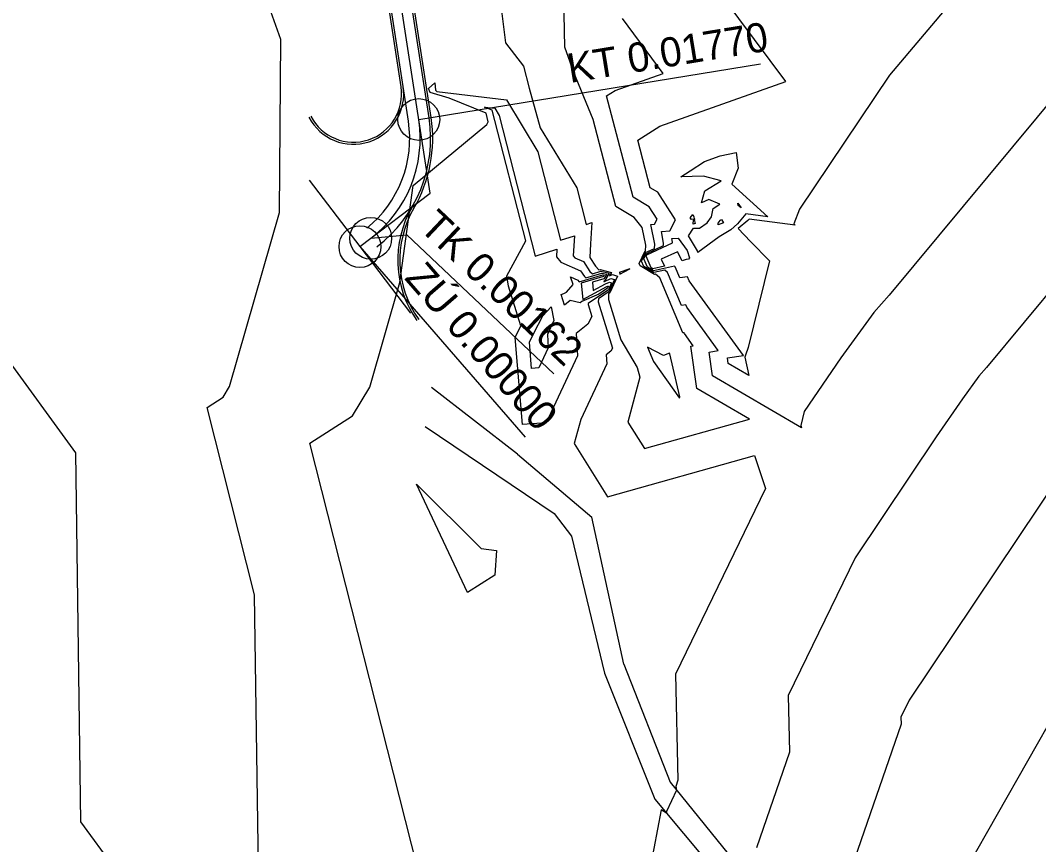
# Model space of a CAD drawing. Extents: x -549394 to -546608, y -1037055 to -1033629.
# Drawn here: x -547937.2 to -547815.5, y -1034670.8 to -1034572.2 of the extents above; entities that cross this region are included whole.
import ezdxf

# ---------------------------------------------------------------- set-up
doc = ezdxf.new("R2010")
doc.units = 0
for name, color, linetype in [('hlavni_vrst', 7, 'Continuous'), ('hrana_L', 7, 'Continuous'), ('norm_vrst', 7, 'Continuous'), ('POLYGONY_SITUACE_PO', 7, 'Continuous'), ('x_navrh_C211', 7, 'Continuous'), ('x_osa_C211', 7, 'Continuous'), ('x_popis_oblouky_C211', 7, 'Continuous'), ('x_popis_pricne_rezy_C211', 7, 'Continuous')]:
    doc.layers.add(name, color=color, linetype=linetype)

msp = doc.modelspace()

# ---------------------------------------------------------------- linework, layer by layer
at = {"layer": 'hlavni_vrst'}
for p, q in [((-547855.39, -1034589.11), (-547853.52, -1034588.45)), ((-547853.52, -1034588.45), (-547851.59, -1034588.02)), ((-547851.59, -1034588.02), (-547851.38, -1034589.9)), ((-547857.11, -1034590.21), (-547855.39, -1034589.11)), ((-547851.38, -1034589.9), (-547852.13, -1034591.83)), ((-547858.22, -1034590.96), (-547857.11, -1034590.21)), ((-547855.5, -1034590.85), (-547858.22, -1034590.96)), ((-547853.38, -1034591.44), (-547855.5, -1034590.85)), ((-547855.35, -1034592.64), (-547853.38, -1034591.44)), ((-547852.13, -1034591.83), (-547847.81, -1034595.73)), ((-547855.76, -1034594.07), (-547855.35, -1034592.64)), ((-547854.86, -1034593.64), (-547855.76, -1034594.07)), ((-547853.54, -1034594.23), (-547854.86, -1034593.64)), ((-547854.55, -1034595.72), (-547854.35, -1034594.72)), ((-547854.35, -1034594.72), (-547853.54, -1034594.23)), ((-547857.09, -1034595.86), (-547856.79, -1034595.47)), ((-547856.93, -1034596.05), (-547857.09, -1034595.86)), ((-547856.67, -1034596.02), (-547856.93, -1034596.05)), ((-547856.79, -1034595.47), (-547856.67, -1034595.74)), ((-547856.75, -1034596.43), (-547856.67, -1034596.02)), ((-547856.67, -1034595.74), (-547856.63, -1034595.97)), ((-547856.63, -1034595.97), (-547856.54, -1034595.99)), ((-547856.54, -1034595.99), (-547856.61, -1034596.04)), ((-547856.61, -1034596.04), (-547856.51, -1034596.53)), ((-547855.08, -1034596.46), (-547854.55, -1034595.72)), ((-547850.46, -1034595.39), (-547851.43, -1034596.58)), ((-547847.81, -1034595.73), (-547850.46, -1034595.39)), ((-547857.31, -1034598.01), (-547856.71, -1034597.1)), ((-547856.75, -1034596.62), (-547856.75, -1034596.43)), ((-547856.51, -1034596.53), (-547856.75, -1034596.62)), ((-547856.71, -1034597.1), (-547855.99, -1034597.1)), ((-547855.99, -1034597.1), (-547855.08, -1034596.46)), ((-547852.25, -1034597.27), (-547853.65, -1034598.14)), ((-547851.43, -1034596.58), (-547852.25, -1034597.27)), ((-547859.29, -1034598.34), (-547858.54, -1034598.29)), ((-547859.21, -1034598.74), (-547859.29, -1034598.34)), ((-547858.54, -1034598.29), (-547857.47, -1034599.77)), ((-547856.22, -1034599.79), (-547857.31, -1034598.01)), ((-547853.65, -1034598.14), (-547856.17, -1034599.98)), ((-547862.27, -1034600.28), (-547859.21, -1034598.83)), ((-547859.21, -1034598.83), (-547859.21, -1034598.74)), ((-547857.47, -1034599.77), (-547857.18, -1034600.64)), ((-547856.17, -1034599.98), (-547856.22, -1034599.79)), ((-547862.35, -1034600.45), (-547862.27, -1034600.28)), ((-547861.77, -1034601.83), (-547862.35, -1034600.45)), ((-547858.62, -1034599.9), (-547860.55, -1034600.8)), ((-547860.55, -1034600.8), (-547860.17, -1034601.64)), ((-547858.05, -1034601.01), (-547858.62, -1034599.9)), ((-547857.6, -1034600.85), (-547858.05, -1034601.01)), ((-547857.3, -1034600.78), (-547857.6, -1034600.85)), ((-547857.18, -1034600.64), (-547857.3, -1034600.78)), ((-547861.56, -1034601.95), (-547861.77, -1034601.83)), ((-547860.17, -1034601.64), (-547861.56, -1034601.95)), ((-547871.41, -1034602.91), (-547870.53, -1034603.29)), ((-547871.07, -1034603.84), (-547871.41, -1034602.91)), ((-547870.53, -1034603.29), (-547870.41, -1034603.48)), ((-547870.36, -1034603.52), (-547867.54, -1034602.68)), ((-547867.48, -1034602.88), (-547870.14, -1034603.67)), ((-547867.54, -1034602.68), (-547867.38, -1034602.72)), ((-547867.38, -1034602.72), (-547867.48, -1034602.88)), ((-547871.87, -1034604.75), (-547871.07, -1034603.84)), ((-547870.41, -1034603.48), (-547870.36, -1034603.52)), ((-547870.14, -1034603.67), (-547869.95, -1034605.6)), ((-547869.95, -1034605.6), (-547867.06, -1034604.07)), ((-547866.97, -1034604.26), (-547868.02, -1034604.99)), ((-547867.06, -1034604.07), (-547866.93, -1034604.01)), ((-547866.86, -1034604.03), (-547866.97, -1034604.26)), ((-547866.93, -1034604.01), (-547866.86, -1034604.03)), ((-547872.51, -1034605.03), (-547872.22, -1034604.89)), ((-547872.11, -1034606.3), (-547872.51, -1034605.03)), ((-547872.22, -1034604.89), (-547871.87, -1034604.75)), ((-547871.44, -1034605.75), (-547872.11, -1034606.3)), ((-547870.26, -1034606.01), (-547871.44, -1034605.75)), ((-547870.06, -1034605.85), (-547870.26, -1034606.01)), ((-547868.02, -1034604.99), (-547870.06, -1034605.85)), ((-547874.72, -1034607.57), (-547873.72, -1034606.48)), ((-547873.72, -1034606.48), (-547873.4, -1034608.13)), ((-547875.77, -1034609.63), (-547874.72, -1034607.57)), ((-547873.4, -1034608.13), (-547874.17, -1034609.82)), ((-547876.31, -1034610.73), (-547875.77, -1034609.63)), ((-547876.06, -1034613.86), (-547876.31, -1034610.73)), ((-547874.17, -1034609.82), (-547874.08, -1034611.38)), ((-547874.08, -1034611.38), (-547875.2, -1034613.8)), ((-547875.2, -1034613.8), (-547876.06, -1034613.86)), ((-547813.16, -1034654.45), (-547828.03, -1034680.56))]:
    msp.add_line(p, q, dxfattribs=at)
at = {"layer": 'hrana_L'}
for p, q in [((-547877.75, -1034624.13), (-547888.02, -1034616.15)), ((-547888.78, -1034620.79), (-547873.35, -1034631.21)), ((-547877.75, -1034624.13), (-547868.85, -1034631.65)), ((-547873.35, -1034631.21), (-547871.3, -1034633.92)), ((-547865.04, -1034649.22), (-547868.85, -1034631.65)), ((-547871.3, -1034633.92), (-547867.33, -1034650.32)), ((-547865.04, -1034649.22), (-547859.51, -1034663.34)), ((-547867.33, -1034650.32), (-547861.32, -1034665.38)), ((-547859.51, -1034663.34), (-547833.31, -1034695.61)), ((-547861.32, -1034665.38), (-547834.9, -1034696.97))]:
    msp.add_line(p, q, dxfattribs=at)
at = {"layer": 'norm_vrst'}
for p, q in [((-547882.84, -1034544.56), (-547879.18, -1034574.92)), ((-547845.65, -1034579.54), (-547858.44, -1034562.37)), ((-547820.19, -1034563.23), (-547833.27, -1034578.79)), ((-547906.03, -1034574.52), (-547908.1, -1034568.67)), ((-547872.08, -1034575.43), (-547872.21, -1034569.2)), ((-547860.31, -1034578.59), (-547865.2, -1034572.02)), ((-547906.18, -1034595.2), (-547906.03, -1034574.52)), ((-547879.18, -1034574.92), (-547877.04, -1034577.71)), ((-547871.01, -1034578.47), (-547872.08, -1034575.43)), ((-547877.04, -1034577.71), (-547876.33, -1034580.33)), ((-547868.69, -1034584.09), (-547871.01, -1034578.47)), ((-547866.08, -1034580.63), (-547860.31, -1034578.59)), ((-547833.27, -1034578.79), (-547844.05, -1034594.82)), ((-547888.36, -1034580.39), (-547887.63, -1034579.69)), ((-547887.63, -1034579.69), (-547887.52, -1034580.57)), ((-547860.73, -1034584.87), (-547845.65, -1034579.54)), ((-547812.36, -1034579.85), (-547833.3, -1034605.08)), ((-547888.19, -1034580.88), (-547888.36, -1034580.39)), ((-547885.9, -1034581.53), (-547888.19, -1034580.88)), ((-547887.52, -1034580.57), (-547887.38, -1034580.75)), ((-547887.38, -1034580.75), (-547879.07, -1034581.73)), ((-547881.5, -1034583.33), (-547885.9, -1034581.53)), ((-547876.33, -1034580.33), (-547875.03, -1034585.08)), ((-547867.09, -1034581.27), (-547866.08, -1034580.63)), ((-547863.92, -1034593.38), (-547867.09, -1034581.27)), ((-547880.78, -1034582.97), (-547881.68, -1034582.6)), ((-547881.68, -1034582.6), (-547880.45, -1034582.75)), ((-547880.45, -1034582.75), (-547879.93, -1034583.6)), ((-547879.07, -1034581.73), (-547875.29, -1034587.94)), ((-547881.24, -1034584.36), (-547881.5, -1034583.33)), ((-547876.75, -1034598.6), (-547880.78, -1034582.97)), ((-547879.93, -1034583.6), (-547875.62, -1034600.45)), ((-547890.21, -1034591.99), (-547881.42, -1034584.7)), ((-547881.42, -1034584.7), (-547881.24, -1034584.36)), ((-547875.03, -1034585.08), (-547870.65, -1034592.27)), ((-547865.97, -1034594.51), (-547868.69, -1034584.09)), ((-547863.37, -1034586.55), (-547860.73, -1034584.87)), ((-547861.88, -1034592.25), (-547863.37, -1034586.55)), ((-547875.29, -1034587.94), (-547872.58, -1034598.54)), ((-547891.8, -1034603.57), (-547890.21, -1034591.99)), ((-547870.65, -1034592.27), (-547869.53, -1034596.64)), ((-547860.97, -1034592.8), (-547861.88, -1034592.25)), ((-547861.99, -1034594.54), (-547863.92, -1034593.38)), ((-547858.85, -1034596.1), (-547860.97, -1034592.8)), ((-547863.8, -1034595.81), (-547865.97, -1034594.51)), ((-547861.04, -1034596.02), (-547861.99, -1034594.54)), ((-547851.39, -1034594.11), (-547850.99, -1034594.65)), ((-547851.38, -1034594.39), (-547851.39, -1034594.11)), ((-547850.99, -1034594.65), (-547851.38, -1034594.39)), ((-547844.05, -1034594.82), (-547844.73, -1034596.56)), ((-547912.15, -1034616.02), (-547906.18, -1034595.2)), ((-547862.82, -1034597.02), (-547863.8, -1034595.81)), ((-547861.35, -1034596.61), (-547861.04, -1034596.02)), ((-547859.53, -1034597.42), (-547858.85, -1034596.1)), ((-547853.52, -1034596.18), (-547853.51, -1034596.13)), ((-547853.51, -1034596.13), (-547853.36, -1034596.03)), ((-547853.36, -1034596.03), (-547853.12, -1034596.46)), ((-547850.07, -1034595.99), (-547850.22, -1034596.18)), ((-547844.56, -1034596.71), (-547850.07, -1034595.99)), ((-547869.53, -1034596.64), (-547868.86, -1034596.41)), ((-547868.86, -1034596.41), (-547869.02, -1034598.96)), ((-547862.4, -1034599.1), (-547862.82, -1034597.02)), ((-547861.8, -1034596.64), (-547861.35, -1034596.61)), ((-547861.34, -1034598.98), (-547861.8, -1034596.64)), ((-547853.12, -1034596.46), (-547853.77, -1034596.68)), ((-547853.77, -1034596.68), (-547853.74, -1034596.49)), ((-547853.74, -1034596.49), (-547853.52, -1034596.18)), ((-547850.22, -1034596.18), (-547851.35, -1034597.13)), ((-547851.35, -1034597.13), (-547849.91, -1034598.68)), ((-547844.73, -1034596.56), (-547844.56, -1034596.71)), ((-547872.58, -1034598.54), (-547870.94, -1034598)), ((-547870.94, -1034598), (-547871.09, -1034600.38)), ((-547860.54, -1034597.49), (-547859.53, -1034597.42)), ((-547860.27, -1034598.86), (-547860.54, -1034597.49)), ((-547879.03, -1034602.8), (-547876.75, -1034598.6)), ((-547875.62, -1034600.45), (-547873.02, -1034599.6)), ((-547873.02, -1034599.6), (-547873.08, -1034600.53)), ((-547869.02, -1034598.96), (-547869.11, -1034600.61)), ((-547862.46, -1034599.84), (-547862.4, -1034599.1)), ((-547862.43, -1034600.01), (-547861.38, -1034599.5)), ((-547862.35, -1034600.15), (-547860.29, -1034599.17)), ((-547861.38, -1034599.5), (-547861.34, -1034598.98)), ((-547860.29, -1034599.17), (-547860.27, -1034598.86)), ((-547849.91, -1034598.68), (-547847.64, -1034601.01)), ((-547873.08, -1034600.53), (-547872.55, -1034601.16)), ((-547871.09, -1034600.38), (-547870.87, -1034600.65)), ((-547870.87, -1034600.65), (-547869.85, -1034601.09)), ((-547869.11, -1034600.61), (-547868.43, -1034601.64)), ((-547863.18, -1034601.31), (-547862.51, -1034599.87)), ((-547862.9, -1034601.03), (-547862.43, -1034600.01)), ((-547862.63, -1034600.74), (-547862.35, -1034600.15)), ((-547862.2, -1034601.74), (-547862.63, -1034600.74)), ((-547862.51, -1034599.87), (-547862.46, -1034599.84)), ((-547872.55, -1034601.16), (-547870.19, -1034602.19)), ((-547870.19, -1034602.19), (-547869.75, -1034602.86)), ((-547869.85, -1034601.09), (-547869.09, -1034602.25)), ((-547868.43, -1034601.64), (-547868, -1034602.06)), ((-547868, -1034602.06), (-547867.86, -1034602.02)), ((-547867.86, -1034602.02), (-547866.49, -1034602.37)), ((-547864.33, -1034601.93), (-547865.57, -1034602.37)), ((-547865.49, -1034602.6), (-547864.33, -1034601.93)), ((-547863.07, -1034601.58), (-547863.18, -1034601.31)), ((-547861.37, -1034602.61), (-547863.07, -1034601.58)), ((-547862.63, -1034601.66), (-547862.9, -1034601.03)), ((-547861.43, -1034602.39), (-547862.63, -1034601.66)), ((-547861.5, -1034602.17), (-547862.2, -1034601.74)), ((-547858.99, -1034601.62), (-547861.5, -1034602.17)), ((-547860.12, -1034602.1), (-547861.43, -1034602.39)), ((-547859.8, -1034602.37), (-547860.12, -1034602.1)), ((-547858.89, -1034601.71), (-547858.99, -1034601.62)), ((-547858.34, -1034603.03), (-547858.89, -1034601.71)), ((-547847.64, -1034601.01), (-547850.19, -1034611.37)), ((-547811.34, -1034601.27), (-547821.7, -1034613.75)), ((-547878.82, -1034604.04), (-547879.03, -1034602.8)), ((-547869.75, -1034602.86), (-547869.57, -1034603.04)), ((-547869.57, -1034603.04), (-547867.65, -1034602.46)), ((-547869.09, -1034602.25), (-547868.79, -1034602.55)), ((-547868.79, -1034602.55), (-547867.76, -1034602.24)), ((-547867.42, -1034603.15), (-547868.79, -1034603.55)), ((-547867.76, -1034602.24), (-547866.79, -1034602.48)), ((-547867.65, -1034602.46), (-547867.08, -1034602.6)), ((-547867.36, -1034603.42), (-547867.43, -1034603.44)), ((-547867.43, -1034603.44), (-547867.42, -1034603.48)), ((-547867.08, -1034602.6), (-547867.42, -1034603.15)), ((-547866.79, -1034602.48), (-547867.36, -1034603.42)), ((-547867.35, -1034603.45), (-547866.57, -1034603.09)), ((-547866.15, -1034603.22), (-547866.79, -1034604.64)), ((-547866.49, -1034602.37), (-547866.76, -1034602.8)), ((-547866.76, -1034602.8), (-547866.39, -1034602.64)), ((-547865.8, -1034602.81), (-547866.7, -1034604.83)), ((-547866.57, -1034603.09), (-547866.15, -1034603.22)), ((-547866.39, -1034602.64), (-547865.8, -1034602.81)), ((-547865.57, -1034602.37), (-547865.44, -1034602.41)), ((-547865.44, -1034602.41), (-547865.49, -1034602.5)), ((-547865.49, -1034602.5), (-547865.49, -1034602.6)), ((-547861.25, -1034602.58), (-547861.37, -1034602.61)), ((-547860.72, -1034603.02), (-547861.25, -1034602.58)), ((-547857.97, -1034609.62), (-547860.72, -1034603.02)), ((-547858.15, -1034606.33), (-547859.8, -1034602.37)), ((-547857.43, -1034602.92), (-547858.34, -1034603.03)), ((-547857.22, -1034603.37), (-547857.43, -1034602.92)), ((-547850.74, -1034612.33), (-547857.22, -1034603.37)), ((-547895.39, -1034616.11), (-547891.8, -1034603.57)), ((-547877.33, -1034608.76), (-547878.82, -1034604.04)), ((-547866.88, -1034604.45), (-547869.28, -1034606.1)), ((-547868.79, -1034603.55), (-547868.69, -1034604.54)), ((-547868.69, -1034604.54), (-547867.21, -1034603.76)), ((-547866.79, -1034604.64), (-547868.07, -1034605.52)), ((-547867.42, -1034603.48), (-547867.35, -1034603.45)), ((-547867.21, -1034603.76), (-547866.75, -1034603.55)), ((-547866.51, -1034603.63), (-547866.88, -1034604.45)), ((-547866.75, -1034603.55), (-547866.51, -1034603.63)), ((-547868.07, -1034605.52), (-547868.08, -1034605.91)), ((-547866.85, -1034604.93), (-547866.87, -1034605.62)), ((-547866.87, -1034605.62), (-547865.4, -1034610.42)), ((-547866.7, -1034604.83), (-547866.85, -1034604.93)), ((-547833.3, -1034605.08), (-547835.14, -1034607.17)), ((-547869.28, -1034606.1), (-547869.29, -1034606.21)), ((-547869.29, -1034606.21), (-547868.85, -1034607.64)), ((-547868.08, -1034605.91), (-547866.39, -1034611.42)), ((-547857.63, -1034606.27), (-547858.15, -1034606.33)), ((-547857.51, -1034606.52), (-547857.63, -1034606.27)), ((-547853.74, -1034611.73), (-547857.51, -1034606.52)), ((-547868.85, -1034607.64), (-547869.34, -1034608.56)), ((-547835.14, -1034607.17), (-547839.08, -1034612.61)), ((-547878.02, -1034610.16), (-547877.33, -1034608.76)), ((-547869.34, -1034608.56), (-547870.73, -1034609.7)), ((-547877.16, -1034620.57), (-547878.02, -1034610.16)), ((-547870.73, -1034609.7), (-547870.58, -1034612.35)), ((-547865.4, -1034610.42), (-547863.43, -1034613.73)), ((-547857.82, -1034609.61), (-547857.97, -1034609.62)), ((-547857.79, -1034609.68), (-547857.82, -1034609.61)), ((-547856.73, -1034611.14), (-547857.79, -1034609.68)), ((-547930.54, -1034623.95), (-547939.34, -1034611.82)), ((-547866.59, -1034611.79), (-547867.14, -1034612.25)), ((-547866.39, -1034611.42), (-547866.59, -1034611.79)), ((-547860.29, -1034612.3), (-547862.19, -1034611.32)), ((-547862.19, -1034611.32), (-547861.5, -1034613.04)), ((-547857.04, -1034611.19), (-547856.73, -1034611.14)), ((-547856.32, -1034616.26), (-547857.04, -1034611.19)), ((-547854.85, -1034611.9), (-547853.74, -1034611.73)), ((-547854.44, -1034614.76), (-547854.85, -1034611.9)), ((-547850.19, -1034611.37), (-547850.5, -1034612.28)), ((-547870.58, -1034612.35), (-547874.32, -1034620.37)), ((-547867.14, -1034612.25), (-547867.08, -1034613.31)), ((-547861.5, -1034613.04), (-547858.39, -1034617.41)), ((-547859.57, -1034612.02), (-547860.29, -1034612.3)), ((-547859.55, -1034612.1), (-547859.57, -1034612.02)), ((-547858.33, -1034617.24), (-547859.55, -1034612.1)), ((-547852.65, -1034612.61), (-547850.74, -1034612.33)), ((-547852.56, -1034613.27), (-547852.65, -1034612.61)), ((-547850.5, -1034612.28), (-547850.55, -1034612.5)), ((-547850.55, -1034612.5), (-547850.1, -1034614.7)), ((-547839.08, -1034612.61), (-547843.48, -1034619.01)), ((-547867.08, -1034613.31), (-547870.18, -1034619.95)), ((-547863.43, -1034613.73), (-547863.1, -1034614.91)), ((-547850.1, -1034614.7), (-547852.56, -1034613.27)), ((-547821.7, -1034613.75), (-547822.61, -1034614.79)), ((-547863.1, -1034614.91), (-547864.54, -1034620.27)), ((-547843.8, -1034620.95), (-547854.44, -1034614.76)), ((-547822.61, -1034614.79), (-547824.57, -1034617.48)), ((-547912.92, -1034617.31), (-547912.15, -1034616.02)), ((-547897.44, -1034619.54), (-547895.39, -1034616.11)), ((-547850.02, -1034619.92), (-547856.32, -1034616.26)), ((-547914.83, -1034618.53), (-547912.92, -1034617.31)), ((-547858.39, -1034617.41), (-547858.33, -1034617.24)), ((-547824.57, -1034617.48), (-547827.69, -1034622.02)), ((-547909.16, -1034640.94), (-547914.83, -1034618.53)), ((-547843.48, -1034619.01), (-547843.86, -1034620.68)), ((-547902.54, -1034622.79), (-547897.44, -1034619.54)), ((-547874.32, -1034620.37), (-547877.16, -1034620.57)), ((-547870.18, -1034619.95), (-547870.95, -1034622.83)), ((-547864.54, -1034620.27), (-547862.57, -1034623.45)), ((-547862.57, -1034623.45), (-547850.02, -1034619.92)), ((-547843.86, -1034620.68), (-547843.8, -1034620.95)), ((-547888.82, -1034677.02), (-547902.54, -1034622.79)), ((-547870.95, -1034622.83), (-547866.99, -1034629.23)), ((-547827.69, -1034622.02), (-547837.37, -1034636.49)), ((-547929.91, -1034668.08), (-547930.54, -1034623.95)), ((-547866.99, -1034629.23), (-547849.4, -1034624.28)), ((-547849.4, -1034624.28), (-547848.08, -1034628.21)), ((-547812.8, -1034626.46), (-547830.92, -1034653.55)), ((-547883.7, -1034640.65), (-547889.81, -1034627.72)), ((-547889.81, -1034627.72), (-547882.08, -1034635.38)), ((-547848.08, -1034628.21), (-547858.84, -1034650.41)), ((-547882.08, -1034635.38), (-547880.23, -1034635.63)), ((-547880.23, -1034635.63), (-547880.46, -1034638.58)), ((-547837.37, -1034636.49), (-547845.37, -1034652.99)), ((-547880.46, -1034638.58), (-547883.7, -1034640.65)), ((-547908.68, -1034674.25), (-547909.16, -1034640.94)), ((-547858.84, -1034650.41), (-547858.58, -1034663.11)), ((-547845.37, -1034652.99), (-547845.23, -1034659.76)), ((-547830.92, -1034653.55), (-547831.91, -1034655.58)), ((-547831.91, -1034655.58), (-547831.89, -1034656.41)), ((-547831.89, -1034656.41), (-547839.52, -1034678.54)), ((-547845.23, -1034659.76), (-547849.18, -1034671.2)), ((-547858.75, -1034664.28), (-547859.95, -1034666.86)), ((-547858.58, -1034663.11), (-547858.83, -1034663.85)), ((-547858.83, -1034663.85), (-547858.74, -1034664.28)), ((-547858.74, -1034664.28), (-547858.75, -1034664.28)), ((-547860.56, -1034666.63), (-547863.27, -1034680.92)), ((-547859.92, -1034667.06), (-547860.56, -1034666.63)), ((-547859.95, -1034666.86), (-547859.92, -1034667.06)), ((-547904.3, -1034703.2), (-547929.91, -1034668.08))]:
    msp.add_line(p, q, dxfattribs=at)
at = {"layer": 'POLYGONY_SITUACE_PO'}
for centre in [(-547889.54, -1034584.09), (-547895.28, -1034598.3), (-547896.57, -1034599.29)]:
    msp.add_circle(centre, 2.5, dxfattribs=at)
at = {"layer": 'x_navrh_C211'}
for p, q in [((-547890.78, -1034584.28), (-547897.39, -1034541.28)), ((-547888.31, -1034583.9), (-547894.91, -1034540.9)), ((-547894.57, -1034599.34), (-547894.52, -1034599.3))]:
    msp.add_line(p, q, dxfattribs=at)
for points in [[(-547891.66, -1034580.17), (-547897.63, -1034541.32)], [(-547888.06, -1034583.87), (-547893.15, -1034550.75)]]:
    msp.add_lwpolyline(points, dxfattribs=at)
for centre, radius, start, end in [((-547897.34, -1034581.05), 6, 207.5618, 8.7374), ((-547897.34, -1034581.05), 5.75, 207.5618, 8.7374), ((-547904.37, -1034586.37), 16.25, 307.3078, 8.7374), ((-547904.37, -1034586.37), 16.5, 329.6518, 8.7374), ((-547904.37, -1034586.37), 13.75, 308.844, 8.7374), ((-547879.56, -1034600.9), 12.5, 149.6518, 215.3627), ((-547879.56, -1034600.9), 12.25, 149.6518, 215.3627)]:
    msp.add_arc(centre, radius, start, end, dxfattribs=at)
at = {"layer": 'x_osa_C211'}
for points in [[(-547888.19, -1034592.9), (-547896.89, -1034536.29), (-547893.86, -1034463.03)], [(-547896.57, -1034599.29), (-547888.19, -1034592.9)]]:
    msp.add_lwpolyline(points, dxfattribs=at)
msp.add_arc((-547904.37, -1034586.37), 15, 307.3078, 8.7374, dxfattribs=at)
at = {"layer": 'x_popis_oblouky_C211'}
msp.add_line((-547895.28, -1034598.3), (-547890.96, -1034597.87), dxfattribs=at)
for points in [[(-547889.54, -1034584.09), (-547848.71, -1034577.44)], [(-547890.96, -1034597.87), (-547873.39, -1034614.51)], [(-547896.57, -1034599.29), (-547876.82, -1034622.06)]]:
    msp.add_lwpolyline(points, dxfattribs=at)
at = {"layer": 'x_popis_pricne_rezy_C211'}
msp.add_lwpolyline([(-547902.63, -1034591.33), (-547896.57, -1034599.29), (-547890.51, -1034607.24)], dxfattribs=at)

# ---------------------------------------------------------------- texts
at = {"layer": 'x_popis_oblouky_C211'}
for s, rotation, p in [('KT 0.01770', 9.2574, (-547871.47, -1034579.73)), ('TK 0.00162', 316.5672, (-547889.63, -1034597.15)), ('ZÚ 0.00000', 310.9356, (-547891.35, -1034603.1))]:
    msp.add_text(s, height=3.5, rotation=rotation, dxfattribs=at).set_placement(p)

doc.saveas('drawing.dxf')
